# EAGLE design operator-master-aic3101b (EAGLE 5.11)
PID: 827
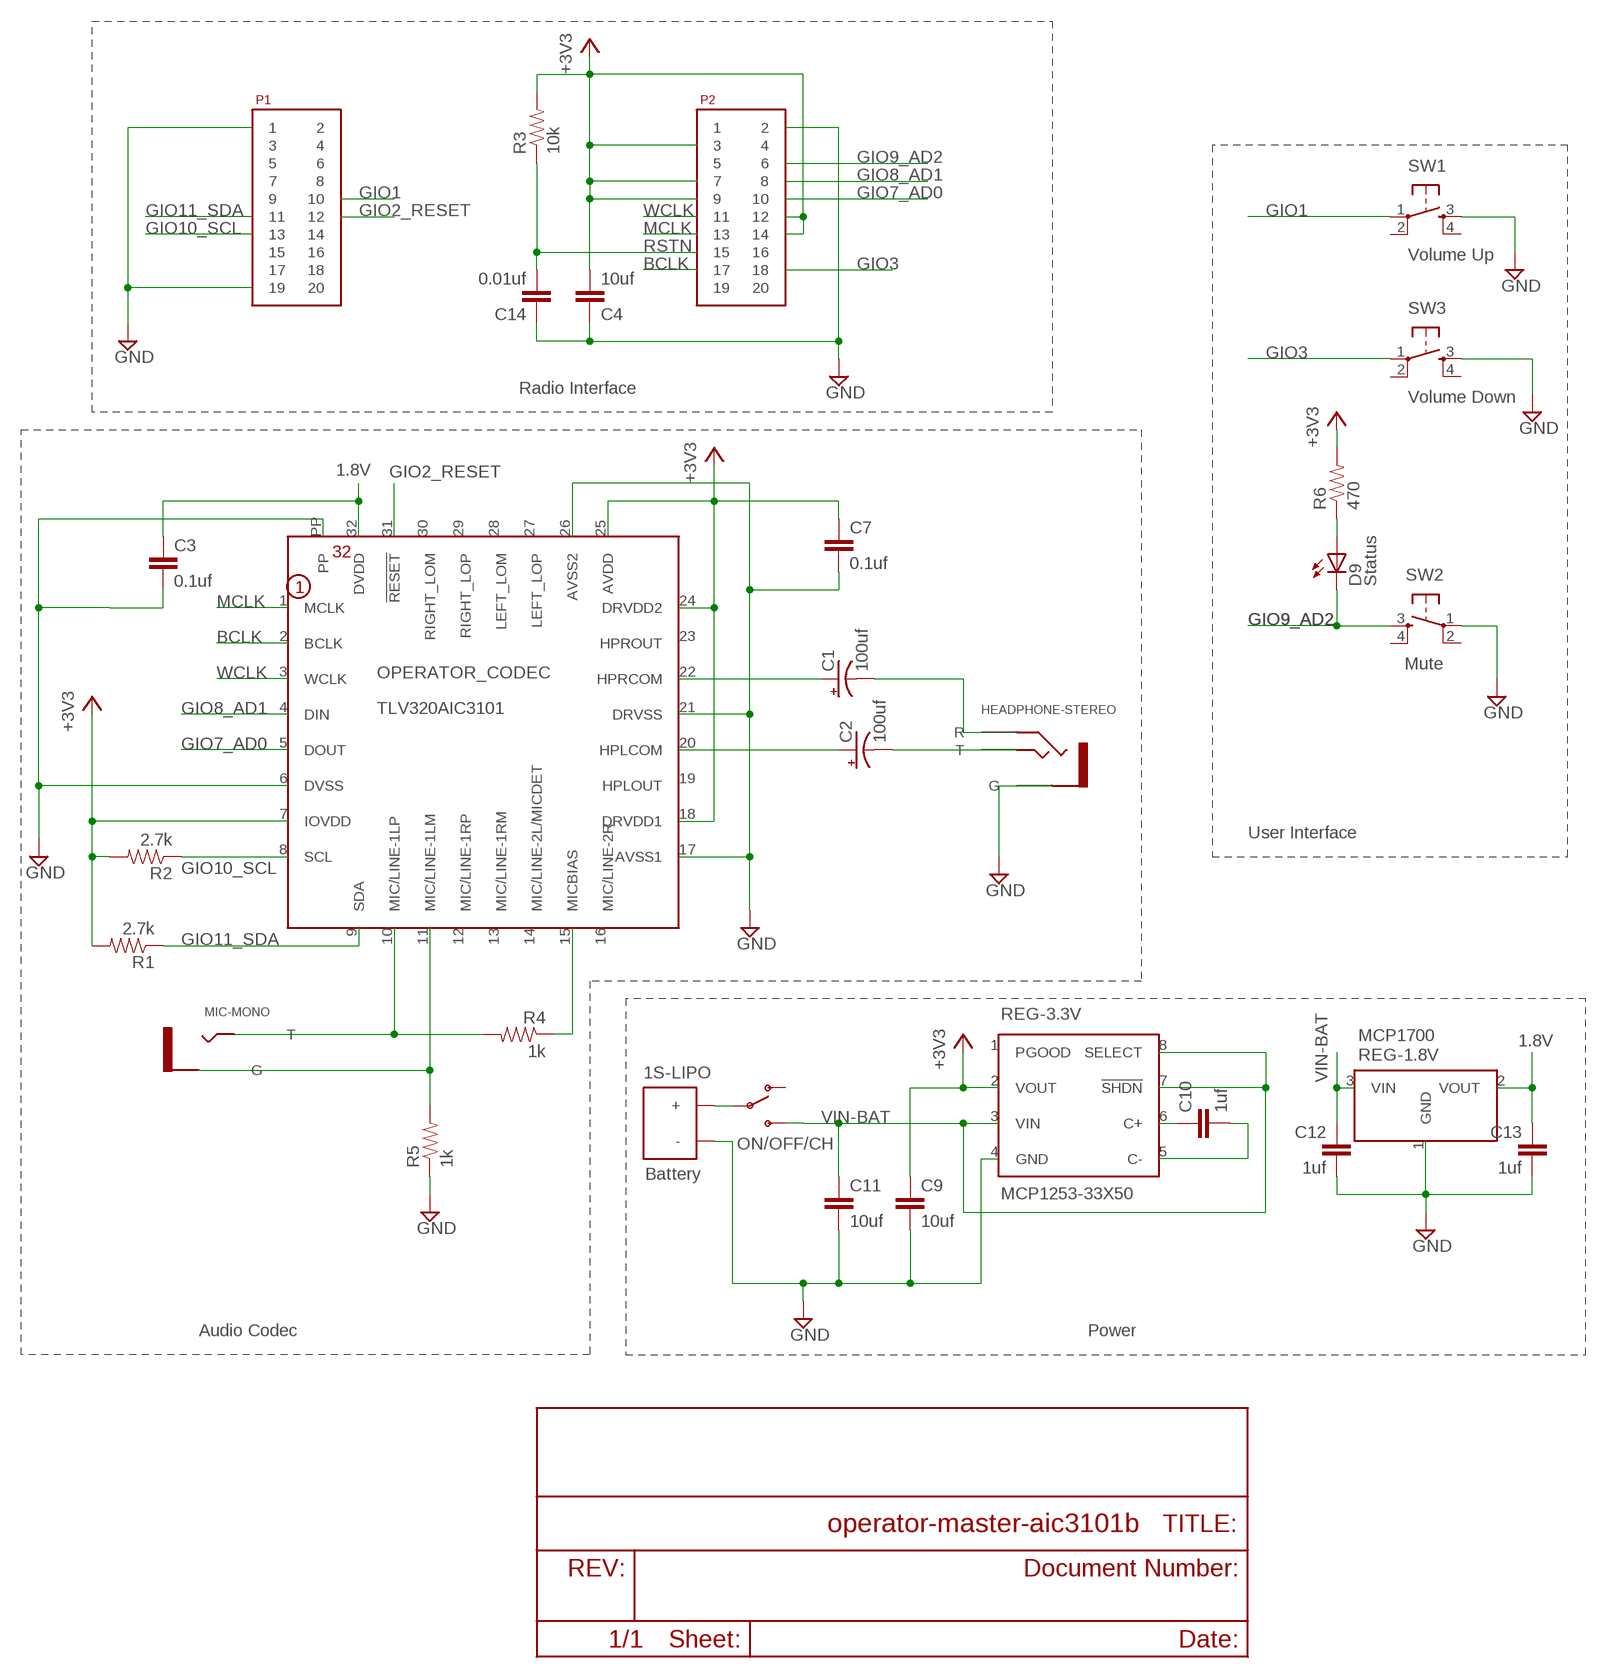
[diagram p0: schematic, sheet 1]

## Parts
1S-LIPO  Battery  JST-2MM-BAT-RIGHT-ANGLE  [JST-2MM-BAT-RIGHT-ANGLE]
C1  100uf  CPOL-USE  [PANASONIC_E]
C2  100uf  CPOL-USE  [PANASONIC_E]
C3  0.1uf  C-EUC1206  [C1206]
C4  10uf  C-EUC1206  [C1206]
C7  0.1uf  C-EUC1206  [C1206]
C9  10uf  C-EUC1206  [C1206]
C10  1uf  C-EUC0805  [C0805]
C11  10uf  C-EUC1206  [C1206]
C12  1uf  C-EUC0805  [C0805]
C13  1uf  C-EUC0805  [C0805]
C14  0.01uf  C-EUC1206  [C1206]
D9  Status  LEDCHIPLED_0805  [CHIPLED_0805]
HEADPHONE-STEREO  HEADPHONE-STEREO-NO-SWITCH  [HEADPHONE-STEREO-NO-SWITCH]
MIC-MONO  MIC-MONO  [MIC-MONO-SWITCH]
ON/OFF/CH  SWITCH-SPSTSMD2  [SWITCH-SPDT-SMD]
OPERATOR_CODEC  TLV320AIC3101  [SCHMARTBOARD-VQFN32-POWERPAD]
P1  SAMTEC-10X2  [SAMTEC-10X2]
P2  SAMTEC-10X2  [SAMTEC-10X2]
R1  2.7k  RESISTOR1206  [1206]
R2  2.7k  RESISTOR1206  [1206]
R3  10k  RESISTOR  [0805]
R4  1k  RESISTOR2010  [R2010]
R5  1k  RESISTOR2010  [R2010]
R6  470  RESISTOR1206  [1206]
REG-1.8V  MCP1700  [SOT23-3]
REG-3.3V  MCP1253-33X50  [8MSOP]
SW1  Volume Up  TAC_SWITCHPTH  [TACTILE-PTH]
SW2  Mute  TAC_SWITCHPTH  [TACTILE-PTH]
SW3  Volume Down  TAC_SWITCHPTH  [TACTILE-PTH]

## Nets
1.8V: C3.1 C13.1 OPERATOR_CODEC.32(DVDD) REG-1.8V.2(VOUT)
+3V3: C4.2 C7.1 C9.1 OPERATOR_CODEC.7(IOVDD) OPERATOR_CODEC.18(DRVDD1) OPERATOR_CODEC.24(DRVDD2) OPERATOR_CODEC.25(AVDD) P2.3 P2.7 P2.9 P2.12 P2.14 R1.2 R2.2 R3.2 R6.2 REG-3.3V.2(VOUT)
BCLK: OPERATOR_CODEC.2(BCLK) P2.17
GIO1: P1.10 SW1.1
GIO2_RESET: OPERATOR_CODEC.31(!RESET) P1.12
GIO3: P2.18 SW3.1
GIO7_AD0: OPERATOR_CODEC.5(DOUT) P2.10
GIO8_AD1: OPERATOR_CODEC.4(DIN) P2.8
GIO9_AD2: D9.C P2.6 SW2.3
GIO10_SCL: OPERATOR_CODEC.8(SCL) P1.13 R2.1
GIO11_SDA: OPERATOR_CODEC.9(SDA) P1.11 R1.1
GND: 1S-LIPO.2(-) C3.2 C4.1 C7.2 C9.2 C11.2 C12.2 C13.2 C14.1 HEADPHONE-STEREO.G OPERATOR_CODEC.6(DVSS) OPERATOR_CODEC.17(AVSS1) OPERATOR_CODEC.21(DRVSS) OPERATOR_CODEC.26(AVSS2) OPERATOR_CODEC.PP P1.1 P1.19 P2.2 R5.1 REG-1.8V.1(GND) REG-3.3V.4(GND) SW1.3 SW2.1 SW3.3
MCLK: OPERATOR_CODEC.1(MCLK) P2.13
MICN: MIC-MONO.G OPERATOR_CODEC.11(MIC/LINE-1LM) R5.2
MICP: MIC-MONO.T OPERATOR_CODEC.10(MIC/LINE-1LP) R4.2
N$2: 1S-LIPO.1(+) ON/OFF/CH.2(P)
N$4: OPERATOR_CODEC.15(MICBIAS) R4.1
N$5: C1.+ OPERATOR_CODEC.22(HPRCOM)
N$6: C2.+ OPERATOR_CODEC.20(HPLCOM)
N$7: C2.- HEADPHONE-STEREO.T
N$8: C1.- HEADPHONE-STEREO.R
N$10: D9.A R6.1
N$11: C10.1 REG-3.3V.6(C+)
N$12: C10.2 REG-3.3V.5(C-)
RSTN: C14.2 P2.15 R3.1
VIN-BAT: C11.1 C12.1 ON/OFF/CH.3(S) REG-1.8V.3(VIN) REG-3.3V.3(VIN) REG-3.3V.7(!SHDN) REG-3.3V.8(SELECT)
WCLK: OPERATOR_CODEC.3(WCLK) P2.11
Unconnected: ON/OFF/CH.1(O) OPERATOR_CODEC.12(MIC/LINE-1RP) OPERATOR_CODEC.13(MIC/LINE-1RM) OPERATOR_CODEC.14(MIC/LINE-2L/MICDET) OPERATOR_CODEC.16(MIC/LINE-2R) OPERATOR_CODEC.19(HPLOUT) OPERATOR_CODEC.23(HPROUT) OPERATOR_CODEC.27(LEFT_LOP) OPERATOR_CODEC.28(LEFT_LOM) OPERATOR_CODEC.29(RIGHT_LOP) OPERATOR_CODEC.30(RIGHT_LOM) P1.2 P1.3 P1.4 P1.5 P1.6 P1.7 P1.8 P1.9 P1.14 P1.15 P1.16 P1.17 P1.18 P1.20 P2.1 P2.4 P2.5 P2.16 P2.19 P2.20 REG-3.3V.1(PGOOD) SW1.2 SW1.4 SW2.2 SW2.4 SW3.2 SW3.4

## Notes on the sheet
- Radio Interface
- User Interface
- Audio Codec | Power

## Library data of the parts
1S-LIPO = trl:JST-2MM-BAT-RIGHT-ANGLE
C1 C2 = rcl:CPOL-US: POLARIZED CAPACITOR, American symbol
C3 C4 C7 C9-C14 = rcl:C-EU: CAPACITOR, European symbol
D9 = led:LED: LED
HEADPHONE-STEREO = trl:HEADPHONE-STEREO-NO-SWITCH
MIC-MONO = trl:MIC-MONO
ON/OFF/CH = SparkFun:SWITCH-SPST: SPST Switch Simple slide switch. Spark Fun Electronics SKU : COM-00102
OPERATOR_CODEC = trl:TLV320AIC3101
P1 P2 = trl:SAMTEC-10X2
R1-R6 = SparkFun:RESISTOR: Resistor
REG-1.8V = trl:MCP1700
REG-3.3V = trl:MCP1253-33X50
SW1-SW3 = SparkFun:TAC_SWITCH: Momentary Switch Button commonly used for reset or general input. Spark Fun Electronics SKU : COM-00097

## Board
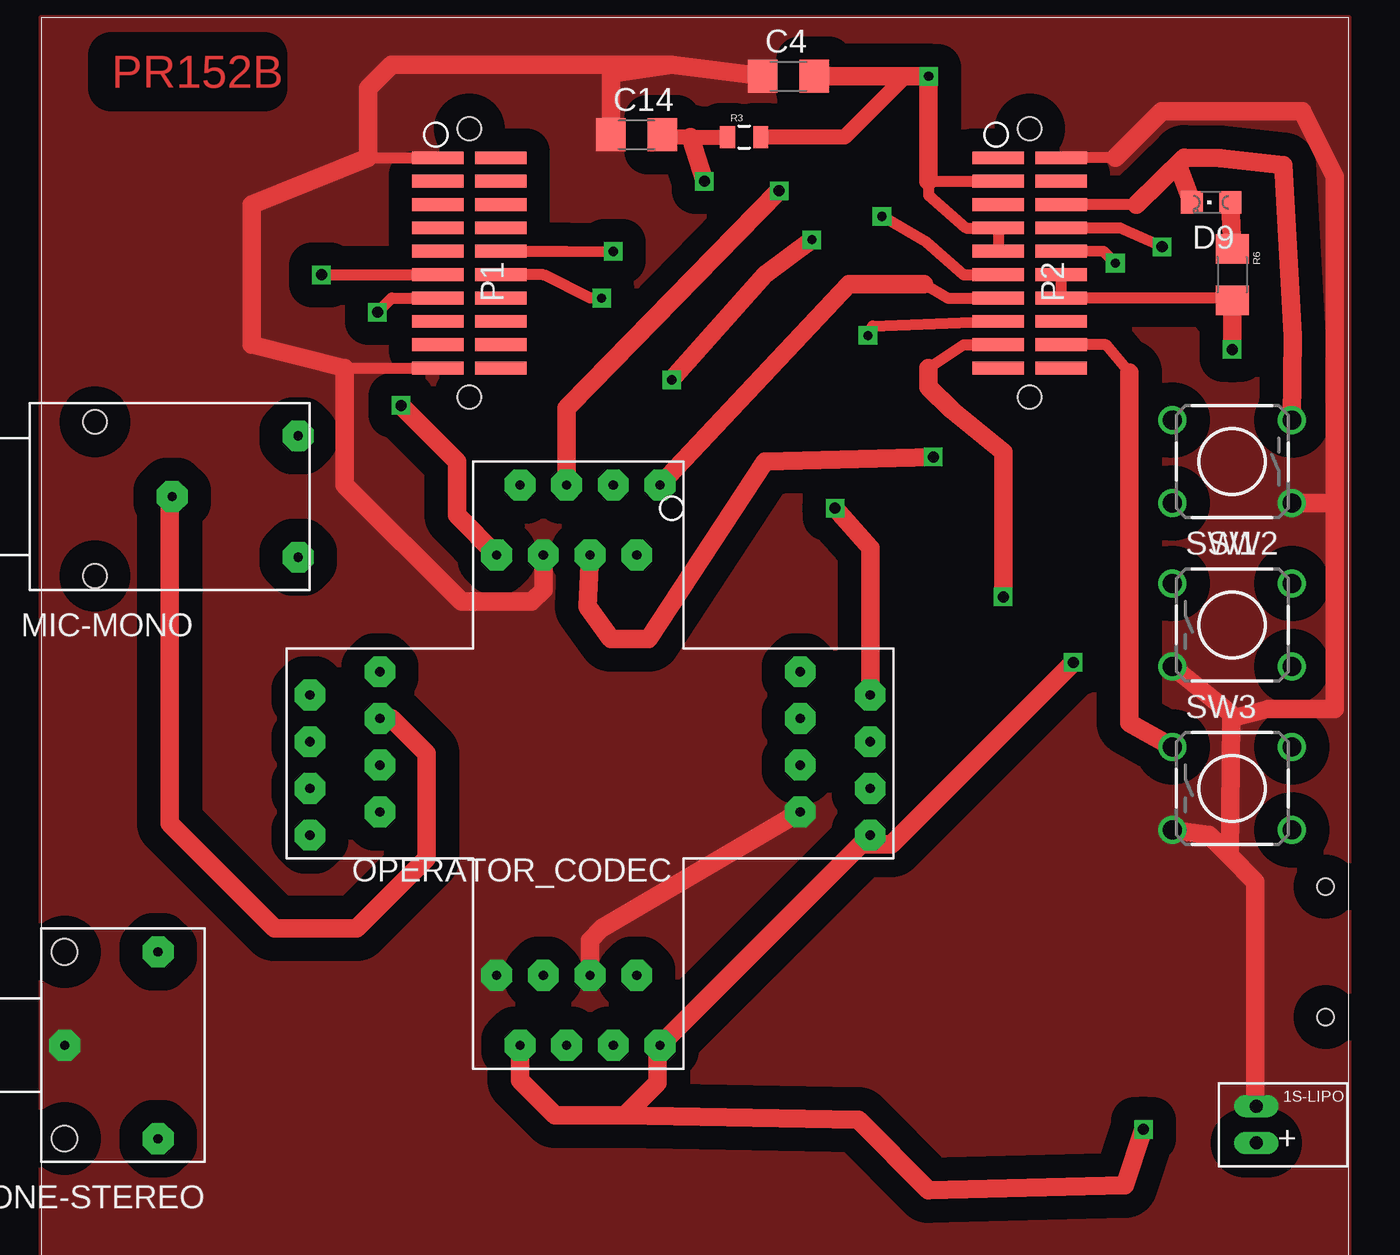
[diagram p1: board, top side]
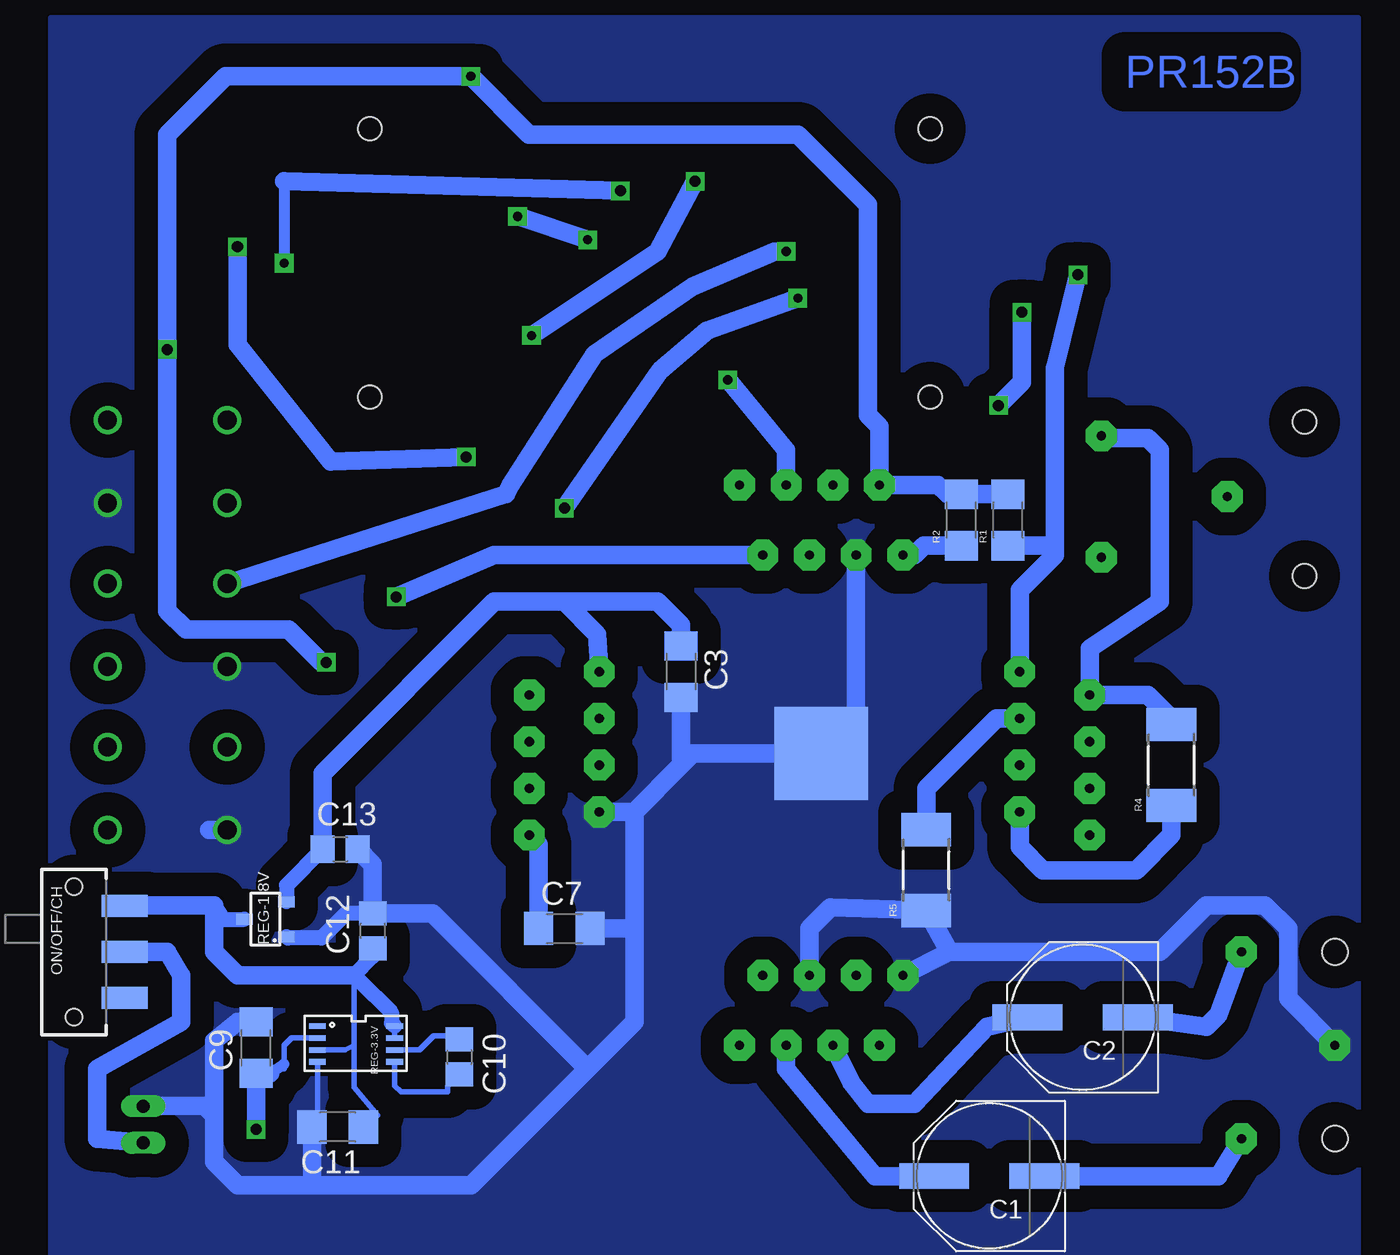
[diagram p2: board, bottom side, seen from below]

No outline drawn. Coordinates in mm, seen from the top.
Copper layers (1*16): Top 0.035mm / dielectric 1.5mm / Bottom 0.035mm
Design rules "default": minimum track width 10mil, minimum drill 24mil, track to track 8mil, track to pad 8mil, pad to pad 8mil, via to via 8mil, smd to smd 8mil, copper to edge 40mil, drill to drill 8mil, minimum pad ring 10mil, minimum via ring 8mil, stop-mask expansion 4mil, vias tented up to drill 0mil, thermal gap 10mil

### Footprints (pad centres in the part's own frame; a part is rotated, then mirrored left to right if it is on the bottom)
JST-2MM-BAT-RIGHT-ANGLE = drill 0.7 pad 1.016 long: 1 -2.5,-1.5; 2 -2.5,0.5
PANASONIC_E = smd 3.8 x 1.4: + 3,0; - -3,0
C1206 = smd 1.6 x 1.8: 1 -1.4,0; 2 1.4,0
C0805 = smd 1.3 x 1.5: 1 -0.95,0; 2 0.95,0
CHIPLED_0805 = smd 1.2 x 1.2: A 0,-1.05; C 0,1.05
HEADPHONE-STEREO-NO-SWITCH = drill 0.5 pad 1.676 octagon: G 5.08,0; R 0,5.08; T 0,-5.08 | hole 1.4: 5.08,5.08; 5.08,-5.08
MIC-MONO-SWITCH = drill 0.5 pad 1.676 octagon: G -2.667,-1.27; SW -9.525,2.032; T -9.525,-4.572 | hole 1.3: 1.524,3.048; 1.524,-5.334
SWITCH-SPDT-SMD = smd 1.2 x 2.5: 1 -2.5,-2.75; 2 0,-2.75; 3 2.5,-2.75 | hole 0.9: -3.55,0; 3.55,0
SCHMARTBOARD-VQFN32-POWERPAD = drill 0.5 pad 1.676 octagon: 1 -4.445,-15.24; 2 -3.175,-11.43; 3 -1.905,-15.24; 4 -0.635,-11.43; 5 0.635,-15.24; 6 1.905,-11.43; 7 3.175,-15.24; 8 4.445,-11.43; 9 10.795,-5.08; 10 14.605,-3.81; 11 10.795,-2.54; 12 14.605,-1.27; 13 10.795,0; 14 14.605,1.27; 15 10.795,2.54; 16 14.605,3.81; 17 4.445,11.43; 18 3.175,15.24; 19 1.905,11.43; 20 0.635,15.24; 21 -0.635,11.43; 22 -1.905,15.24; 23 -3.175,11.43; 24 -4.445,15.24; 25 -15.875,3.81; 26 -12.065,2.54; 27 -15.875,1.27; 28 -12.065,0; 29 -15.875,-1.27; 30 -12.065,-2.54; 31 -15.875,-3.81; 32 -12.065,-5.08 | smd 5.08 x 5.08 bottom: PP 0,-0.635
SAMTEC-10X2 = smd 0.7 x 2.8: 1 -6.358,-1.296; 2 -6.358,2.134; 3 -5.088,-1.296; 4 -5.088,2.134; 5 -3.818,-1.296; 6 -3.818,2.134; 7 -2.548,-1.296; 8 -2.548,2.134; 9 -1.278,-1.296; 10 -1.278,2.134; 11 -0.008,-1.296; 12 -0.008,2.134; 13 1.262,-1.296; 14 1.262,2.134; 15 2.532,-1.296; 16 2.532,2.134; 17 3.802,-1.296; 18 3.802,2.134; 19 5.072,-1.296; 20 5.072,2.134 | hole 1.27: -7.938,0.42; 6.66,0.42
1206 = smd 1.6 x 1.8: 1 -1.4,0; 2 1.4,0
0805 = smd 0.8 x 1.2: 1 -0.9,0; 2 0.9,0
R2010 = smd 1.8 x 2.7: 1 -2.2,0; 2 2.2,0
SOT23-3 = smd 0.6 x 0.9: 1 -0.95,-1.15; 2 0.95,-1.15; 3 0,1.15
8MSOP = smd 0.3 x 0.9: 1 -1.05,-2; 2 -0.4,-2; 3 0.25,-2; 4 0.9,-2; 5 0.9,2.2; 6 0.25,2.2; 7 -0.4,2.2; 8 -1.05,2.2
TACTILE-PTH = drill 1.016 round: 1 -3.251,2.261; 2 3.251,2.261; 3 -3.251,-2.261; 4 3.251,-2.261

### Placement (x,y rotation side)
1S-LIPO  68.58,7.62 0 top
C1  20.07,4.32 180 bottom
C2  14.99,12.95 180 bottom
C3  36.83,31.75 270 bottom
C4  40.64,64.14 0 top
C7  43.18,17.78 0 bottom
C9  59.94,11.3 90 bottom
C10  48.9,10.79 270 bottom
C11  55.5,6.99 180 bottom
C12  53.59,17.65 90 bottom
C13  55.37,22.1 0 bottom
C14  32.38,60.96 0 top
D9  63.63,57.28 90 top
HEADPHONE-STEREO  6.35,11.43 180 top
MIC-MONO  4.45,40.01 180 top
ON/OFF/CH  69.85,16.51 90 bottom
OPERATOR_CODEC  29.21,26.67 180 top
P1  22.86,53.34 270 top
P2  53.34,53.34 270 top
R1  19.05,40.01 90 bottom
R2  21.59,40.01 90 bottom
R3  38.23,60.83 0 top
R4  10.16,26.67 90 bottom
R5  23.5,20.95 90 bottom
R6  64.77,53.34 270 top
REG-1.8V  59.44,18.29 90 bottom
REG-3.3V  54.61,11.43 270 bottom
SW1  64.77,34.29 0 top
SW2  64.77,43.18 180 top
SW3  64.77,25.4 0 top

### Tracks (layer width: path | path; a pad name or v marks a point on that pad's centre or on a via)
1.8V
  Bottom 0.813: REG-1.8V.2 58.29,20.13 C13.1
  Bottom 1.016: C13.1 56.32,26.23 46.99,35.56 43.18,35.56 | 43.18,35.56 41.4,33.78 OPERATOR_CODEC.32 | C3.1 36.83,34.29 38.1,35.56 43.18,35.56
+3V3  (via drill 0.5 pad 1.02, 0.6 pad 0.61)
  Top 0.61: P2.9 P2.7 50.29,55.88 48.26,57.66 48.26,58.42 P2.3 | P2.12 P2.14 64.63,52.08 R6.2
  Top 0.813: R3.2 43.69,60.83 46.99,64.14
  Top 1.016: v48.26,64.14 46.99,64.14 C4.2 | OPERATOR_CODEC.18 26.04,9.53 27.94,7.62 31.5,7.62 | 31.5,7.62 31.75,7.62 33.53,9.4 33.53,11.3 OPERATOR_CODEC.24 44.58,22.36 | 44.58,22.36 OPERATOR_CODEC.25 | v59.94,6.86 58.93,3.81 48.26,3.56 44.45,7.37 31.5,7.62 | 44.58,22.36 46.23,22.36 v56.13,32.26 | v64.77,49.28 R6.2 | v48.26,64.14 48.26,58.42 | v48.26,64.14
  Bottom 0.305: REG-3.3V.2 58.02,11.83 58.42,11.43 58.42,10.41 58.42,10.16
  Bottom 0.61: 59.18,9.91 58.42,10.41
  Bottom 1.016: C7.1 44.58,22.36 OPERATOR_CODEC.25 | R1.2 R2.2 22.36,41.41 22.86,41.91 OPERATOR_CODEC.7 26.04,45.09 26.67,45.72 26.67,57.15 30.48,60.96 45.09,60.96 v48.26,64.14 61.59,64.14 64.77,60.96 v64.77,49.28 64.77,35.05 63.75,34.04 58.17,34.04 56.39,32.26 v56.13,32.26 | v59.94,6.86 C9.1 59.18,9.91
BCLK  (via drill 0.6 pad 0.41)
  Top 0.61: P2.17 50.16,49.53 48.26,48.26
  Top 1.016: v52.32,35.81 52.32,43.69 49.53,45.97 48.26,47.24 48.26,48.26
  Bottom 1.016: OPERATOR_CODEC.2 46.99,38.1 v52.32,35.81
GIO1  (via drill 0.5 pad 1.02)
  Top 0.61: P1.10 28.57,54.62 v31.11,54.61
  Bottom 1.016: v31.11,54.61 31.75,54.61 36.2,52.7 41.53,49.02 46.1,41.91 46.35,41.4 SW1.1
GIO2_RESET  (via drill 0.5 pad 1.02, 0.6)
  Top 0.61: v30.48,52.07 29.84,52.07 27.3,53.34 25,53.34 P1.12
  Top 1.016: OPERATOR_CODEC.31 45.09,38.48 v43.18,40.64
  Bottom 1.016: v30.48,52.07 35.43,50.29 37.97,48.13 v43.18,40.64
GIO3
  Top 0.61: P2.18 57.91,49.53 59.18,48.01
  Top 1.016: 59.18,48.01 59.18,28.96 SW3.1
GIO7_AD0  (via drill 0.5 pad 1.02, 0.6 pad 0.61)
  Top 0.61: P2.10 57.78,54.61 v58.42,53.98
  Top 1.016: OPERATOR_CODEC.5 28.57,46.1 28.7,46.23 v40.13,57.91
  Bottom 0.61: 58.42,58.42 v58.42,53.98
  Bottom 1.016: v40.13,57.91 58.42,58.42
GIO8_AD1  (via drill 0.6 pad 0.61)
  Top 0.61: P2.8 58.67,55.88 v60.96,54.86
  Top 1.016: v48.51,43.43 39.37,43.18 33.02,33.53 30.99,33.53 29.72,35.31 OPERATOR_CODEC.4
  Bottom 1.016: v60.96,54.86 60.96,49.53 55.88,43.18 v48.51,43.43
GIO9_AD2
  Top 0.61: P2.6 59.7,57.16 59.56,57.15
  Top 1.016: 62.16,59.71 64.14,59.69 67.56,59.31 68.07,50.04 SW2.3 | 62.16,59.71 59.56,57.15 | D9.C 61.85,59.26 62.16,59.71
GIO10_SCL  (via drill 0.6 pad 0.41)
  Top 0.61: P1.13 19.06,52.08 v18.29,51.31
  Top 1.016: v19.56,46.23 22.61,43.18 22.61,40.26 OPERATOR_CODEC.8
  Bottom 1.016: R2.1 23.62,38.6 24.13,38.1 OPERATOR_CODEC.8 | v18.29,51.31 18.29,47.5 v19.56,46.23
GIO11_SDA  (via drill 0.6)
  Top 0.61: v15.24,53.34 P1.11
  Bottom 1.016: OPERATOR_CODEC.9 18.41,36.2 16.51,38.1 | 16.51,38.1 16.51,48.26 v15.24,53.34 | R1.1 17.02,38.6 16.51,38.1
GND
  Top 0.61: 58.42,59.7 P2.2 | 17.79,59.7 P1.1 | 16.51,48.26 P1.19
  Top 1.016: SW3.3 63.5,22.86 64.64,21.72 | 64.64,21.72 66.04,20.32 66.04,8.16 1S-LIPO.2 | OPERATOR_CODEC.21 29.84,17.14 30.48,17.78 OPERATOR_CODEC.26 | OPERATOR_CODEC.6 27.3,36.2 26.67,35.56 22.86,35.56 16.51,41.91 16.51,48.26 11.43,49.53 11.43,57.15 17.79,59.7 17.78,59.71 17.78,63.5 19.05,64.77 34.29,64.77 | 60.96,62.23 58.42,59.7 | 60.96,62.23 60.97,62.24 | 60.96,62.23 68.58,62.23 70.36,58.67 70.36,40.64 | 34.29,64.77 C4.1 | C14.1 30.98,64.27 34.29,64.77 | 70.36,40.64 70.36,29.72 66.75,29.72 64.71,29.21 | 64.64,21.72 64.71,29.21 | 64.71,29.21 64.72,29.46 SW1.3 | SW2.1 70.08,40.92 70.36,40.64
  Bottom 0.305: REG-3.3V.4 56.61,7.27 C11.2
  Bottom 0.813: 1S-LIPO.2 | C12.2 55.06,18.6 56.39,17.27 58.22,17.27 REG-1.8V.1 | 54.61,3.81 57.15,3.81 57.91,3.81 | 62.36,7.75 62.23,7.87
  Bottom 1.016: 39.37,24.13 36.83,26.67 | 36.83,26.67 36.2,27.3 OPERATOR_CODEC.PP 27.3,29.21 OPERATOR_CODEC.6 | OPERATOR_CODEC.26 39.37,24.13 | 22.23,16.51 R5.1 28.7,18.92 29.84,17.78 OPERATOR_CODEC.21 | 22.23,16.51 10.79,16.51 8.26,19.05 5.08,19.05 3.81,17.78 3.81,13.97 HEADPHONE-STEREO.G | 22.23,16.51 OPERATOR_CODEC.17 | 61.54,23.11 SW3.3 62.51,23.14 | 39.37,17.78 C7.2 | 39.37,24.13 39.37,17.78 | 54.16,21.84 C13.2 53.59,21.27 C12.2 50.35,18.6 41.91,10.16 | 36.83,26.67 C3.2 | 1S-LIPO.2 62.74,8.13 62.36,7.75 62.23,7.62 62.23,5.08 60.96,3.81 54.61,3.81 48.26,3.81 41.91,10.16 | 41.91,10.16 39.37,12.7 39.37,17.78 | C11.2 56.9,4.06 57.15,3.81 | 62.23,7.87 62.23,11.68 60.96,12.7 C9.2
  pour Top (isolate 1.27, no thermals): 0,67.31 71.12,67.31 71.12,0 0,0
  pour Bottom (isolate 1.27, no thermals): 0,67.31 71.12,67.31 71.12,0 0,0
MCLK
  Top 0.61: P2.13 49.28,52.07 48.01,52.83
  Top 1.016: OPERATOR_CODEC.1 43.94,52.83 48.01,52.83
MICN
  Top 1.016: OPERATOR_CODEC.11 19.05,29.21 20.95,27.3 20.95,21.59 17.14,17.78 12.7,17.78 6.99,23.5 6.99,41.15 MIC-MONO.G
  Bottom 1.016: R5.2 23.5,25.4 19.68,29.21 OPERATOR_CODEC.11
MICP
  Bottom 1.016: R4.2 10.16,29.21 11.43,30.48 OPERATOR_CODEC.10 14.61,33.02 10.79,35.56 10.79,43.81 11.43,44.45 14.1,44.45 MIC-MONO.T
N$2
  Bottom 1.016: ON/OFF/CH.2 64.77,16.51 64.01,15.24 64.01,12.7 68.58,10.16 68.58,6.35 1S-LIPO.1
N$4
  Bottom 1.016: OPERATOR_CODEC.15 18.41,22.23 17.14,20.95 12.06,20.95 10.16,22.86 R4.1
N$5
  Bottom 1.016: OPERATOR_CODEC.22 31.11,10.16 26.29,4.32 C1.+
N$6
  Bottom 1.016: C2.+ 20.19,12.45 24.13,8.26 26.67,8.26 27.56,9.4 OPERATOR_CODEC.20
N$7
  Bottom 1.016: C2.- 8.26,12.45 7.62,13.08 HEADPHONE-STEREO.T
N$8
  Bottom 1.016: C1.- 7.62,4.32 HEADPHONE-STEREO.R
N$10
  Top 0.406: R6.1 64.22,54.2
  Top 1.016: R6.1 D9.A
N$11
  Bottom 0.305: REG-3.3V.6 51.05,11.18 50.29,11.94 49.09,11.94 C10.1
N$12
  Bottom 0.305: REG-3.3V.5 52.41,9.23 52.07,8.89 49.53,8.89 49.53,9.21 C10.2
RSTN  (via drill 0.5 pad 1.02, 0.6 pad 0.61)
  Top 0.61: P2.15 45.22,50.55 v44.96,50.04
  Top 0.813: R3.1 35.31,60.83 33.91,60.83 C14.2
  Top 1.016: v36.07,58.42 35.31,60.83
  Bottom 1.016: v44.96,50.04 38.1,54.61 v36.07,58.42
VIN-BAT
  Bottom 0.305: REG-3.3V.8 REG-3.3V.7 | 54.36,14.99 54.61,14.73 54.61,11.43 | C11.1 53.46,7.62 53.34,7.62 54.61,9.14 54.61,11.43 | REG-3.3V.3 55.11,11.18 54.61,11.43
  Bottom 0.813: REG-1.8V.3 61.72,18.29 62.23,19.05 | 67.06,19.05 ON/OFF/CH.3 | C12.1 53.59,16.26 54.61,15.24 54.36,14.99 52.58,13.21 52.58,12.65 REG-3.3V.8
  Bottom 1.016: 67.06,19.05 62.23,19.05 62.23,16.51 60.96,15.24 54.61,15.24
WCLK  (via drill 0.5 pad 1.02)
  Top 0.61: P2.11 50.16,53.34 48.13,55.12 v45.72,56.52
  Top 1.016: v41.91,55.24 39.37,53.34 v34.29,47.62
  Bottom 1.016: v41.91,55.24 v45.72,56.52 | v34.29,47.62 31.11,43.81 OPERATOR_CODEC.3

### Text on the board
Top: PR152B
Bottom: PR152B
